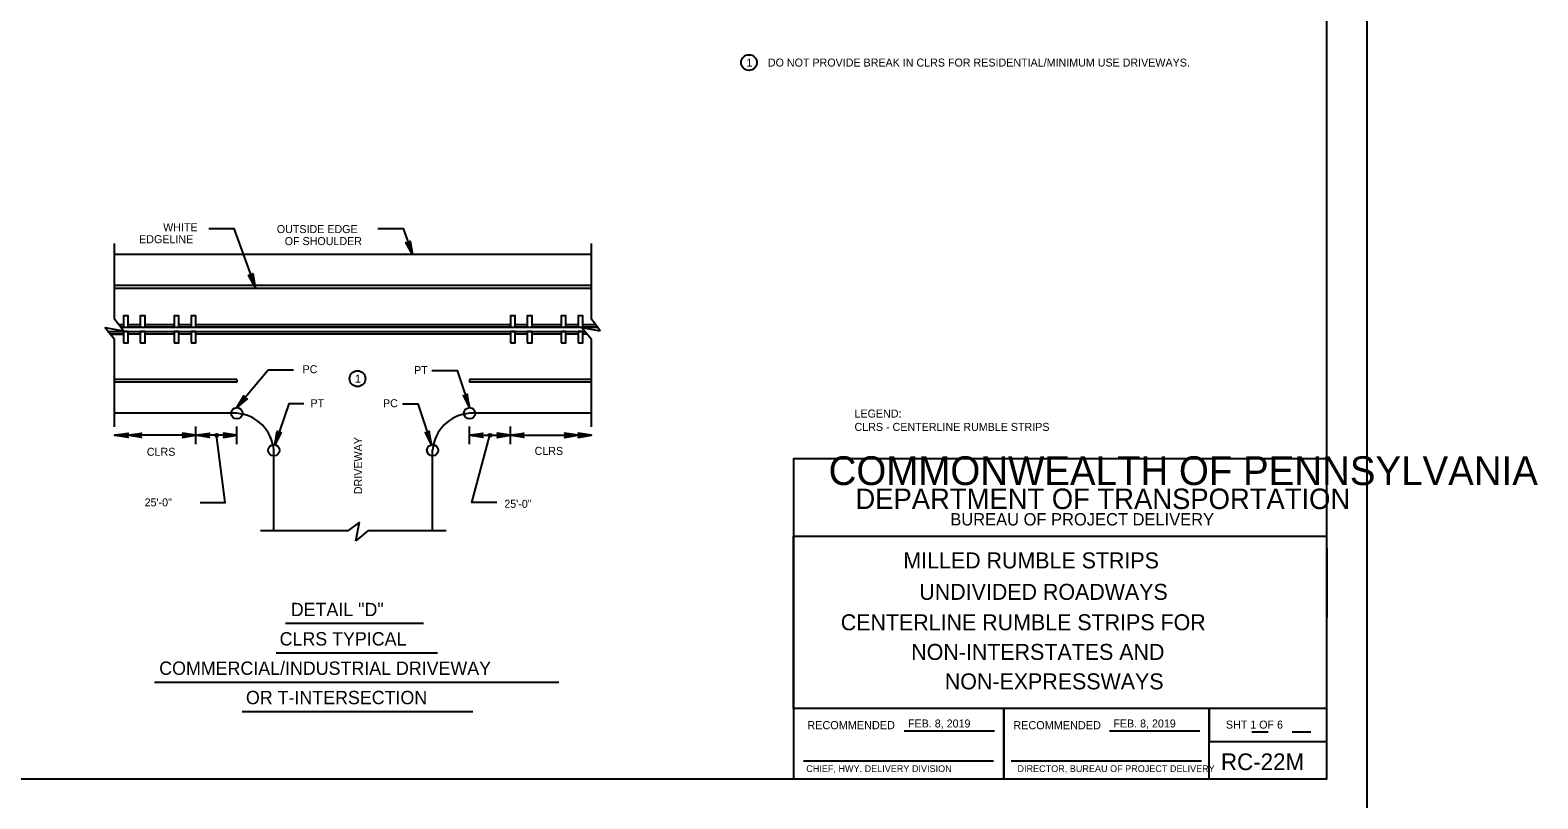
# Model space of a CAD drawing. Extents: x 632008 to 634206, y 294231 to 297795.
# Drawn here: x 632348 to 632913, y 297208 to 297496 of the extents above; entities that cross this region are included whole.
import ezdxf

# ---------------------------------------------------------------- set-up
doc = ezdxf.new("R2010")
doc.units = 0
for name, color, linetype in [('1', 7, 'Continuous'), ('3', 7, 'Continuous'), ('Level 2', 7, 'Continuous'), ('PLT-BNDY', 7, 'Continuous')]:
    doc.layers.add(name, color=color, linetype=linetype)

msp = doc.modelspace()

# ---------------------------------------------------------------- linework, layer by layer
at = {"layer": '1'}
for p, q in [((632425.07, 297365.39), (632425.07, 297364.33)), ((632512.36, 297365.39), (632512.36, 297364.33)), ((632833.86, 297302.19), (632833.86, 297276.04)), ((632833.86, 297234.5), (632833.86, 297297.33)), ((632443.32, 297274.04), (632495.08, 297274.04)), ((632439.8, 297262.82), (632500.28, 297262.82)), ((632394.23, 297251.82), (632545.85, 297251.82)), ((632427.12, 297240.82), (632513.53, 297240.82)), ((632675.32, 297233.61), (632709.21, 297233.61)), ((632752.32, 297233.61), (632786.19, 297233.61)), ((632805.73, 297233.3), (632811.87, 297233.3)), ((632820.79, 297233.3), (632827.89, 297233.3)), ((632637.64, 297222.43), (632708.89, 297222.43)), ((632715.49, 297222.43), (632786.83, 297222.43))]:
    msp.add_line(p, q, dxfattribs=at)
msp.add_lwpolyline([(632833.86, 297215.62), (632833.86, 297779.62), (632047.86, 297779.62), (632047.86, 297215.62), (632833.86, 297215.62), (632833.86, 297241.98), (632633.86, 297241.98), (632633.86, 297306.66), (632833.86, 297306.66), (632833.86, 297335.62), (632633.86, 297335.62), (632633.86, 297215.62), (632712.66, 297215.62), (632712.66, 297241.98), (632712.66, 297215.62), (632789.66, 297215.62), (632789.66, 297241.98), (632789.66, 297229.66), (632833.86, 297229.66)], dxfattribs=at)
for points in [[(632382.52, 297384.93), (632381.51, 297384.93), (632380.72, 297385.99), (632382.52, 297385.99)], [(632384.38, 297385.99), (632388.85, 297385.99), (632388.85, 297384.93), (632384.38, 297384.93)], [(632390.71, 297385.99), (632401.52, 297385.99), (632401.52, 297384.93), (632390.71, 297384.93)], [(632403.38, 297385.99), (632407.91, 297385.99), (632407.91, 297384.93), (632403.38, 297384.93)], [(632409.75, 297385.99), (632527.65, 297385.99), (632527.65, 297384.93), (632409.75, 297384.93)], [(632529.51, 297385.99), (632533.98, 297385.99), (632533.98, 297384.93), (632529.51, 297384.93)], [(632535.84, 297385.99), (632546.65, 297385.99), (632546.65, 297384.93), (632535.84, 297384.93)], [(632548.51, 297385.99), (632553.04, 297385.99), (632553.04, 297384.93), (632548.51, 297384.93)], [(632554.89, 297385.99), (632559.52, 297385.99), (632560.31, 297384.93), (632554.89, 297384.93)], [(632382.52, 297382.3), (632377.69, 297382.3), (632376.84, 297383.35), (632382.52, 297383.35)], [(632384.37, 297383.35), (632388.84, 297383.35), (632388.84, 297382.3), (632384.37, 297382.3)], [(632390.7, 297383.35), (632401.5, 297383.35), (632401.5, 297382.3), (632390.7, 297382.3)], [(632403.36, 297383.35), (632407.89, 297383.35), (632407.89, 297382.29), (632403.36, 297382.29)], [(632409.74, 297383.35), (632527.64, 297383.35), (632527.64, 297382.29), (632409.74, 297382.29)], [(632529.5, 297383.35), (632533.97, 297383.35), (632533.97, 297382.29), (632529.5, 297382.29)], [(632535.83, 297383.35), (632546.63, 297383.35), (632546.63, 297382.29), (632535.83, 297382.29)], [(632548.49, 297383.35), (632553.02, 297383.35), (632553.02, 297382.29), (632548.49, 297382.29)], [(632554.88, 297383.35), (632555.63, 297383.35), (632556.48, 297382.29), (632554.88, 297382.29)]]:
    msp.add_lwpolyline(points, close=True, dxfattribs=at)
at = {"layer": '3'}
for p, q in [((632409.74, 297341.11), (632409.74, 297347.72)), ((632425.07, 297341.11), (632425.07, 297347.72)), ((632512.34, 297341.15), (632512.34, 297347.76)), ((632527.68, 297341.15), (632527.68, 297347.76)), ((632425.07, 297344.41), (632379.24, 297344.41)), ((632512.34, 297344.45), (632558.07, 297344.45))]:
    msp.add_line(p, q, dxfattribs=at)
for points in [[(632446.29, 297368.81), (632436.87, 297368.81), (632425.07, 297354.79)], [(632498.23, 297368.77), (632507.65, 297368.77), (632512.34, 297354.79)], [(632428.63, 297358.07), (632428.25, 297358.16), (632425.07, 297354.79), (632428.63, 297358.07), (632428.95, 297358.12), (632425.07, 297354.79), (632427.88, 297358.46), (632427.73, 297358.81), (632425.07, 297354.79), (632427.72, 297359.16), (632427.73, 297358.81)], [(632450.22, 297356.27), (632444.52, 297356.27), (632439.35, 297340.89)], [(632487.2, 297356.27), (632492.9, 297356.27), (632498.07, 297340.89)], [(632510.24, 297359.15), (632510.63, 297359.09), (632512.34, 297354.79), (632510.24, 297359.15), (632509.97, 297359.31), (632512.34, 297354.79), (632511.09, 297359.24), (632511.36, 297359.51), (632512.34, 297354.79), (632511.5, 297359.83), (632511.36, 297359.51)], [(632384.03, 297343.81), (632383.86, 297344.16), (632379.24, 297344.41), (632384.03, 297343.81), (632384.28, 297343.6), (632379.24, 297344.41), (632383.85, 297344.64), (632384.02, 297344.98), (632379.24, 297344.41), (632384.28, 297345.21), (632384.02, 297344.98)], [(632389.05, 297343.81), (632388.88, 297344.16), (632384.26, 297344.41), (632389.05, 297343.81), (632389.3, 297343.6), (632384.26, 297344.41), (632388.87, 297344.64), (632389.04, 297344.98), (632384.26, 297344.41), (632389.3, 297345.21), (632389.04, 297344.98)], [(632404.94, 297343.81), (632405.12, 297344.16), (632409.74, 297344.41), (632404.94, 297343.81), (632404.69, 297343.6), (632409.74, 297344.41), (632405.12, 297344.64), (632404.95, 297344.98), (632409.74, 297344.41), (632404.69, 297345.21), (632404.95, 297344.98)], [(632414.53, 297343.81), (632414.35, 297344.16), (632409.74, 297344.41), (632414.53, 297343.81), (632414.78, 297343.6), (632409.74, 297344.41), (632414.35, 297344.64), (632414.52, 297344.98), (632409.74, 297344.41), (632414.78, 297345.21), (632414.52, 297344.98)], [(632420.28, 297343.81), (632420.45, 297344.16), (632425.07, 297344.41), (632420.28, 297343.81), (632420.03, 297343.6), (632425.07, 297344.41), (632420.46, 297344.64), (632420.29, 297344.98), (632425.07, 297344.41), (632420.03, 297345.21), (632420.29, 297344.98)], [(632441.45, 297345.24), (632441.06, 297345.18), (632439.35, 297340.89), (632441.45, 297345.24), (632441.73, 297345.41), (632439.35, 297340.89), (632440.6, 297345.33), (632440.33, 297345.6), (632439.35, 297340.89), (632440.2, 297345.92), (632440.33, 297345.6)], [(632495.97, 297345.24), (632496.35, 297345.18), (632498.07, 297340.89), (632495.97, 297345.24), (632495.69, 297345.41), (632498.07, 297340.89), (632496.81, 297345.33), (632497.08, 297345.6), (632498.07, 297340.89), (632497.22, 297345.92), (632497.08, 297345.6)], [(632517.14, 297343.85), (632516.96, 297344.2), (632512.34, 297344.45), (632517.14, 297343.85), (632517.38, 297343.64), (632512.34, 297344.45), (632516.96, 297344.68), (632517.12, 297345.02), (632512.34, 297344.45), (632517.38, 297345.25), (632517.12, 297345.02)], [(632522.89, 297343.85), (632523.06, 297344.2), (632527.68, 297344.45), (632522.89, 297343.85), (632522.64, 297343.64), (632527.68, 297344.45), (632523.07, 297344.68), (632522.9, 297345.02), (632527.68, 297344.45), (632522.64, 297345.25), (632522.9, 297345.02)], [(632532.47, 297343.85), (632532.3, 297344.2), (632527.68, 297344.45), (632532.47, 297343.85), (632532.72, 297343.64), (632527.68, 297344.45), (632532.29, 297344.68), (632532.46, 297345.02), (632527.68, 297344.45), (632532.72, 297345.25), (632532.46, 297345.02)], [(632548.26, 297343.85), (632548.43, 297344.2), (632553.05, 297344.45), (632548.26, 297343.85), (632548.01, 297343.64), (632553.05, 297344.45), (632548.44, 297344.68), (632548.27, 297345.02), (632553.05, 297344.45), (632548.01, 297345.25), (632548.27, 297345.02)], [(632553.28, 297343.85), (632553.45, 297344.2), (632558.07, 297344.45), (632553.28, 297343.85), (632553.03, 297343.64), (632558.07, 297344.45), (632553.46, 297344.68), (632553.29, 297345.02), (632558.07, 297344.45), (632553.03, 297345.25), (632553.29, 297345.02)], [(632411.27, 297319.21), (632420.69, 297319.21), (632417.5, 297344.41)], [(632522.59, 297319.21), (632513.17, 297319.21), (632519.98, 297344.44)]]:
    msp.add_lwpolyline(points, dxfattribs=at)
for centre, radius in [((632617.15, 297484.16), 2.95), ((632470.32, 297365.65), 2.95), ((632425.07, 297352.68), 2.11), ((632512.34, 297352.68), 2.11), ((632417.5, 297344.41), 0.581), ((632519.98, 297344.44), 0.581), ((632438.94, 297338.81), 2.11), ((632498.47, 297338.81), 2.11)]:
    msp.add_circle(centre, radius, dxfattribs=at)
at = {"layer": 'Level 2'}
for p, q in [((632379.24, 297387.97), (632379.24, 297416.27)), ((632558.04, 297387.97), (632558.04, 297416.27)), ((632558.04, 297412.21), (632379.24, 297412.21)), ((632558.04, 297400.56), (632379.24, 297400.56)), ((632558.04, 297399.51), (632379.24, 297399.51)), ((632375.59, 297384.89), (632382.56, 297383.54)), ((632379.24, 297380.38), (632375.59, 297384.89)), ((632382.56, 297383.54), (632379.24, 297387.97)), ((632380.72, 297385.99), (632382.53, 297385.99)), ((632381.51, 297384.93), (632466.76, 297384.93)), ((632384.38, 297385.99), (632388.86, 297385.99)), ((632390.71, 297385.99), (632401.53, 297385.99)), ((632403.38, 297385.99), (632407.86, 297385.99)), ((632407.86, 297385.99), (632407.91, 297385.99)), ((632409.75, 297385.99), (632501.43, 297385.99)), ((632451.88, 297384.93), (632523.83, 297384.93)), ((632501.43, 297385.99), (632527.65, 297385.99)), ((632508.95, 297385.99), (632512.24, 297385.99)), ((632508.95, 297384.93), (632560.31, 297384.93)), ((632529.5, 297385.99), (632529.56, 297385.99)), ((632529.51, 297385.99), (632533.92, 297385.99)), ((632529.51, 297385.99), (632533.99, 297385.99)), ((632535.84, 297385.99), (632539.25, 297385.99)), ((632535.84, 297385.99), (632546.66, 297385.99)), ((632548.51, 297385.99), (632552.99, 297385.99)), ((632558.03, 297380.38), (632554.39, 297384.89)), ((632554.39, 297384.89), (632561.36, 297383.54)), ((632554.89, 297385.99), (632559.52, 297385.99)), ((632561.36, 297383.54), (632558.04, 297387.97)), ((632376.84, 297383.35), (632466.76, 297383.35)), ((632377.69, 297382.3), (632382.52, 297382.3)), ((632379.24, 297347.63), (632379.24, 297380.38)), ((632407.85, 297382.3), (632407.91, 297382.3)), ((632451.88, 297383.35), (632523.83, 297383.35)), ((632558.03, 297347.63), (632558.03, 297380.38)), ((632425.07, 297365.39), (632379.24, 297365.39)), ((632425.07, 297364.33), (632379.24, 297364.33)), ((632558.03, 297365.39), (632512.36, 297365.39)), ((632558.03, 297364.33), (632512.36, 297364.33)), ((632425.07, 297352.68), (632379.24, 297352.68)), ((632558.03, 297352.68), (632512.34, 297352.68)), ((632438.94, 297308.54), (632438.94, 297338.81)), ((632498.47, 297308.54), (632498.47, 297338.81)), ((632471.07, 297311.86), (632466.64, 297308.54)), ((632469.72, 297304.9), (632471.07, 297311.86)), ((632466.64, 297308.54), (632433.89, 297308.54)), ((632474.23, 297308.54), (632469.72, 297304.9)), ((632503.52, 297308.54), (632474.23, 297308.54))]:
    msp.add_line(p, q, dxfattribs=at)
for points in [[(632414.56, 297422.01), (632423.97, 297422.01), (632431.98, 297400.01)], [(632478.01, 297422.01), (632487.42, 297422.01), (632490.99, 297412.21)], [(632489.91, 297416.92), (632489.64, 297416.64), (632490.99, 297412.21), (632489.91, 297416.92), (632490.02, 297417.23), (632490.99, 297412.21), (632489.19, 297416.47), (632488.81, 297416.51), (632490.99, 297412.21), (632488.5, 297416.67), (632488.81, 297416.51)], [(632430.9, 297404.72), (632430.64, 297404.44), (632431.98, 297400.01), (632430.9, 297404.72), (632431.01, 297405.03), (632431.98, 297400.01), (632430.18, 297404.27), (632429.8, 297404.31), (632431.98, 297400.01), (632429.5, 297404.48), (632429.8, 297404.31)], [(632508.95, 297383.35), (632555.63, 297383.35), (632555.63, 297383.35)]]:
    msp.add_lwpolyline(points, dxfattribs=at)
for points in [[(632382.52, 297384.93), (632384.37, 297384.93), (632384.37, 297389.16), (632382.52, 297389.16)], [(632388.85, 297384.93), (632390.7, 297384.93), (632390.7, 297389.16), (632388.85, 297389.16)], [(632401.52, 297384.93), (632403.36, 297384.93), (632403.36, 297389.16), (632401.52, 297389.16)], [(632407.91, 297384.93), (632409.75, 297384.93), (632409.75, 297389.16), (632407.91, 297389.16)], [(632527.65, 297384.93), (632529.5, 297384.93), (632529.5, 297389.15), (632527.65, 297389.15)], [(632527.65, 297384.93), (632529.5, 297384.93), (632529.5, 297389.15), (632527.65, 297389.15)], [(632533.98, 297384.93), (632535.83, 297384.93), (632535.83, 297389.15), (632533.98, 297389.15)], [(632533.98, 297384.93), (632535.83, 297384.93), (632535.83, 297389.15), (632533.98, 297389.15)], [(632546.65, 297384.93), (632548.49, 297384.93), (632548.49, 297389.15), (632546.65, 297389.15)], [(632553.04, 297384.93), (632554.88, 297384.93), (632554.88, 297389.15), (632553.04, 297389.15)], [(632382.52, 297379.13), (632384.37, 297379.13), (632384.37, 297383.35), (632382.52, 297383.35)], [(632388.85, 297379.13), (632390.7, 297379.13), (632390.7, 297383.35), (632388.85, 297383.35)], [(632401.52, 297379.13), (632403.36, 297379.13), (632403.36, 297383.35), (632401.52, 297383.35)], [(632407.91, 297379.13), (632409.75, 297379.13), (632409.75, 297383.35), (632407.91, 297383.35)], [(632527.65, 297379.13), (632529.5, 297379.13), (632529.5, 297383.35), (632527.65, 297383.35)], [(632527.65, 297379.13), (632529.5, 297379.13), (632529.5, 297383.35), (632527.65, 297383.35)], [(632533.98, 297379.13), (632535.83, 297379.13), (632535.83, 297383.35), (632533.98, 297383.35)], [(632533.98, 297379.13), (632535.83, 297379.13), (632535.83, 297383.35), (632533.98, 297383.35)], [(632546.65, 297379.13), (632548.49, 297379.13), (632548.49, 297383.35), (632546.65, 297383.35)], [(632553.04, 297379.13), (632554.88, 297379.13), (632554.88, 297383.35), (632553.04, 297383.35)]]:
    msp.add_lwpolyline(points, close=True, dxfattribs=at)
for centre, start, end in [((632423.79, 297337.53), 4.837, 85.163), ((632513.63, 297337.53), 94.837, 175.163)]:
    msp.add_arc(centre, 15.21, start, end, dxfattribs=at)
at = {"layer": 'PLT-BNDY'}
msp.add_lwpolyline([(632007.86, 297794.62), (632848.86, 297794.62), (632848.86, 297200.62), (632007.86, 297200.62)], close=True, dxfattribs=at)

# ---------------------------------------------------------------- texts
at = {"layer": '1'}
for s, height, p in [('LEGEND:', 3, (632656.72, 297351.07)), ('CLRS - CENTERLINE RUMBLE STRIPS', 3, (632656.72, 297346.07)), ('COMMONWEALTH OF PENNSYLVANIA', 10.7834, (632647.01, 297325.77)), ('DEPARTMENT OF TRANSPORTATION', 7.6843, (632657.07, 297316.77)), ('BUREAU OF PROJECT DELIVERY', 4.6221, (632692.65, 297310.61)), ('MILLED RUMBLE STRIPS', 6, (632675.02, 297294.52)), ('UNDIVIDED ROADWAYS', 6, (632681.02, 297282.73)), ('CENTERLINE RUMBLE STRIPS FOR', 6, (632651.56, 297271.32)), ('NON-INTERSTATES AND', 6, (632677.99, 297260.2)), ('NON-EXPRESSWAYS', 6, (632690.59, 297249.16)), ('FEB. 8, 2019', 3, (632676.78, 297234.87)), ('FEB. 8, 2019', 3, (632753.78, 297234.87)), ('RECOMMENDED', 3.048, (632639.02, 297234.22)), ('RECOMMENDED', 3.048, (632716.27, 297234.2)), ('SHT 1 OF 6', 3, (632795.99, 297234.45)), ('RC-22M', 6.267, (632794.14, 297218.88))]:
    msp.add_text(s, height=height, dxfattribs=at).set_placement(p)
for s, p in [('CHIEF, HWY. DELIVERY DIVISION', (632638.62, 297218.17)), ('DIRECTOR, BUREAU OF PROJECT DELIVERY', (632717.83, 297218.17))]:
    msp.add_text(s, height=2.54, rotation=360, dxfattribs=at).set_placement(p)
at = {"layer": '3'}
for s, p in [('PC', (632449.72, 297367.69)), ('PT', (632491.54, 297367.37)), ('PT', (632452.67, 297354.94)), ('PC', (632479.88, 297354.94)), ('CLRS', (632391.32, 297336.74)), ('CLRS', (632536.74, 297337.07)), ('25\'-0"', (632390.48, 297317.78)), ('25\'-0"', (632525.38, 297317.23))]:
    msp.add_text(s, height=3, dxfattribs=at).set_placement(p)
msp.add_text('DRIVEWAY', height=3, rotation=90, dxfattribs=at).set_placement((632472.06, 297322.34))
at = {"layer": 'Level 2'}
for s, height, p in [('1', 3, (632616.18, 297482.66)), ('DO NOT PROVIDE BREAK IN CLRS FOR RESIDENTIAL/MINIMUM USE DRIVEWAYS.', 3, (632624.22, 297482.66)), ('EDGELINE', 3, (632388.43, 297416.44)), ('WHITE', 3, (632397.43, 297420.94)), ('OUTSIDE EDGE', 3, (632440.06, 297420.23)), ('OF SHOULDER', 3, (632443.03, 297415.73)), ('1', 3, (632469.35, 297364.15)), ('DETAIL "D"', 5, (632445.3, 297276.61)), ('CLRS TYPICAL', 5, (632441.12, 297265.61)), ('COMMERCIAL/INDUSTRIAL DRIVEWAY', 5, (632395.96, 297254.61)), ('OR T-INTERSECTION', 5, (632428.48, 297243.61))]:
    msp.add_text(s, height=height, dxfattribs=at).set_placement(p)

doc.saveas('drawing.dxf')
